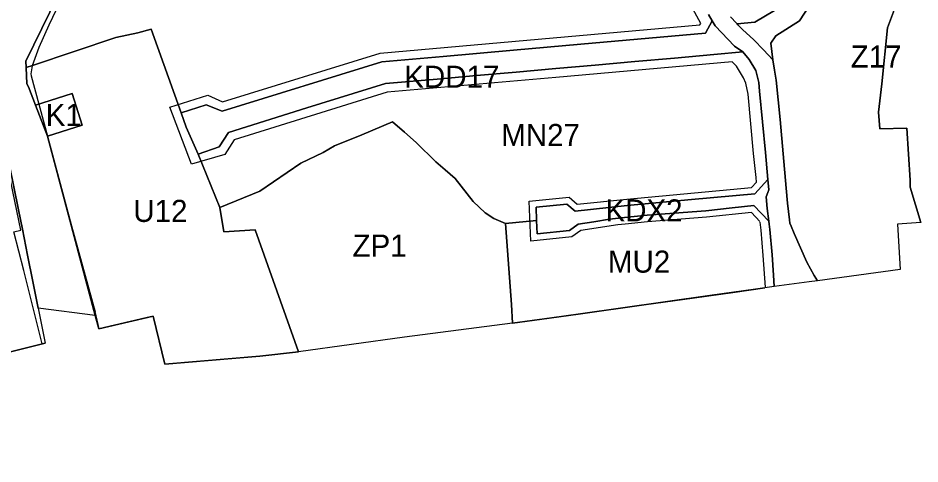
# Model space of a CAD drawing. Extents: x 7428841 to 7433518, y 5545054 to 5546840.
# Drawn here: x 7430252.9 to 7430661.7, y 5545108.1 to 5545310.2 of the extents above; entities that cross this region are included whole.
import ezdxf

# ---------------------------------------------------------------- set-up
doc = ezdxf.new("R2010")
doc.units = 0
for name, color, linetype in [('linie_rozgraniczajace', 7, 'Continuous'), ('linie_zabudowy_nieprzekraczalne', 7, 'Continuous'), ('oznaczenia_przeznaczen', 7, 'Continuous')]:
    doc.layers.add(name, color=color, linetype=linetype)

msp = doc.modelspace()

# ---------------------------------------------------------------- linework, layer by layer
at = {"layer": 'linie_rozgraniczajace'}
for points in [[(7430671.62, 5545396.42), (7430655.46, 5545383.04), (7430607.04, 5545308.84), (7430596.43, 5545302.16), (7430594.11, 5545298.72), (7430595.04, 5545291.17), (7430590.74, 5545295.75), (7430586.44, 5545300.33), (7430581.24, 5545305.02), (7430579.2, 5545307.11), (7430578.85, 5545307.47), (7430586.92, 5545308.36), (7430599.81, 5545316.06), (7430649.43, 5545392.37), (7430667.19, 5545405.74)], [(7430649.64, 5545312.97), (7430646.98, 5545305.71), (7430644.46, 5545280.38), (7430642.86, 5545267.43), (7430643.58, 5545259.98), (7430655.75, 5545260.21), (7430657.29, 5545236.72), (7430657.25, 5545233.5), (7430662.16, 5545217.46), (7430651.46, 5545216.69), (7430652.67, 5545196.27), (7430615.27, 5545191.14), (7430613.75, 5545193.47), (7430612.07, 5545196.52), (7430610.38, 5545199.57), (7430604.66, 5545212.59), (7430603.27, 5545215.9), (7430602.78, 5545217.26), (7430602.6, 5545218.73), (7430601.68, 5545226.2), (7430601.12, 5545233.04), (7430599.73, 5545248.63), (7430598.34, 5545264.21), (7430597.45, 5545273.08), (7430596.56, 5545281.95), (7430595.8, 5545286.56), (7430595.04, 5545291.17), (7430594.11, 5545298.72), (7430596.43, 5545302.16), (7430607.04, 5545308.84), (7430655.46, 5545383.04)], [(7430662.16, 5545217.46), (7430657.25, 5545233.5), (7430657.29, 5545236.72), (7430655.75, 5545260.21), (7430643.58, 5545259.98), (7430642.86, 5545267.43), (7430644.46, 5545280.38), (7430646.98, 5545305.71), (7430649.64, 5545312.97), (7430650.17, 5545314.36), (7430651.98, 5545318.53), (7430653.8, 5545322.71), (7430656.52, 5545327.37), (7430659.25, 5545332.04), (7430665.45, 5545338.74)], [(7430270.86, 5545320.33), (7430256.41, 5545290.6), (7430256.53, 5545287.68), (7430256.83, 5545280.36), (7430256.83, 5545280.35), (7430257.64, 5545278.96), (7430260.84, 5545270.63), (7430266.24, 5545256.61), (7430287.9, 5545175.34), (7430262, 5545178.72), (7430259.61, 5545190.72), (7430257.22, 5545202.69), (7430254.87, 5545214.45), (7430253.11, 5545223.25), (7430249.09, 5545243.33)], [(7430256.53, 5545287.68), (7430256.41, 5545290.6), (7430270.86, 5545320.33)], [(7430599.81, 5545316.06), (7430586.92, 5545308.36), (7430578.85, 5545307.47), (7430578.5, 5545307.83), (7430575.76, 5545310.63)], [(7430565.79, 5545311.83), (7430567.55, 5545308.83), (7430564.46, 5545303.28), (7430507.94, 5545298.3), (7430477.42, 5545295.59), (7430445.6, 5545292.79), (7430417.77, 5545290.33), (7430345.45, 5545267.96), (7430338.13, 5545270.81)], [(7430575.76, 5545310.63), (7430578.5, 5545307.83), (7430578.85, 5545307.47), (7430579.2, 5545307.11), (7430581.24, 5545305.02), (7430586.44, 5545300.33), (7430590.74, 5545295.75), (7430595.04, 5545291.17), (7430595.8, 5545286.56), (7430596.56, 5545281.95), (7430597.45, 5545273.08), (7430598.34, 5545264.21), (7430599.73, 5545248.63), (7430601.12, 5545233.04), (7430601.68, 5545226.2), (7430602.6, 5545218.73), (7430602.78, 5545217.26), (7430603.27, 5545215.9), (7430604.66, 5545212.59), (7430610.38, 5545199.57), (7430612.07, 5545196.52), (7430613.75, 5545193.47), (7430615.27, 5545191.14), (7430611.44, 5545190.62), (7430595.63, 5545188.44), (7430595.27, 5545193.69), (7430594.63, 5545202.81), (7430593.67, 5545214.38), (7430593.34, 5545216.69), (7430593.16, 5545218.14), (7430592.45, 5545223.91), (7430591.93, 5545229.07), (7430592.68, 5545231.05), (7430593.15, 5545232.36), (7430592.73, 5545237.03), (7430591.64, 5545249.22), (7430589.01, 5545277.08), (7430588.63, 5545280.9), (7430587.25, 5545286.36), (7430584.28, 5545291.3), (7430581.4, 5545294.77), (7430577.64, 5545297.41), (7430568.85, 5545306.6), (7430567.55, 5545308.83), (7430565.79, 5545311.83)], [(7430338.13, 5545270.81), (7430326.79, 5545267.2), (7430313.2, 5545305.05), (7430307.25, 5545303.45), (7430297.25, 5545301.41), (7430259.45, 5545288.63), (7430256.53, 5545287.68)], [(7430249.09, 5545243.33), (7430253.11, 5545223.25), (7430254.87, 5545214.45), (7430257.22, 5545202.69), (7430259.61, 5545190.72), (7430262, 5545178.72), (7430265.18, 5545162.82), (7430244.43, 5545157.62)]]:
    msp.add_lwpolyline(points, dxfattribs=at)
for points in [[(7430326.79, 5545267.2), (7430338.13, 5545270.81), (7430345.45, 5545267.96), (7430417.77, 5545290.33), (7430445.6, 5545292.79), (7430477.42, 5545295.59), (7430507.94, 5545298.3), (7430564.46, 5545303.28), (7430567.55, 5545308.83), (7430568.85, 5545306.6), (7430577.64, 5545297.41), (7430581.4, 5545294.77), (7430568.3, 5545293.58), (7430550.37, 5545292), (7430532.44, 5545290.42), (7430514.51, 5545288.83), (7430496.58, 5545287.25), (7430478.65, 5545285.66), (7430460.72, 5545284.09), (7430442.79, 5545282.5), (7430419.39, 5545280.44), (7430383.81, 5545269.4), (7430348.24, 5545258.36), (7430343.99, 5545251.76), (7430334.46, 5545248.51), (7430329.12, 5545260.68)], [(7430256.83, 5545280.35), (7430256.83, 5545280.36), (7430256.53, 5545287.68), (7430259.45, 5545288.63), (7430297.25, 5545301.41), (7430307.25, 5545303.45), (7430313.2, 5545305.05), (7430326.79, 5545267.2), (7430329.12, 5545260.68), (7430334.46, 5545248.51), (7430344.35, 5545224.34), (7430346.16, 5545213.28), (7430360.34, 5545214.12), (7430380.07, 5545158.83), (7430362.43, 5545156.9), (7430319.38, 5545153.37), (7430314.08, 5545175.08), (7430310.82, 5545174.3), (7430289.52, 5545169.27), (7430287.9, 5545175.34), (7430266.24, 5545256.61), (7430282, 5545261.6), (7430277.46, 5545275.9), (7430260.84, 5545270.63), (7430257.64, 5545278.96)], [(7430334.46, 5545248.51), (7430343.99, 5545251.76), (7430348.24, 5545258.36), (7430383.81, 5545269.4), (7430419.39, 5545280.44), (7430442.79, 5545282.5), (7430460.72, 5545284.09), (7430478.65, 5545285.66), (7430496.58, 5545287.25), (7430514.51, 5545288.83), (7430532.44, 5545290.42), (7430550.37, 5545292), (7430568.3, 5545293.58), (7430581.4, 5545294.77), (7430584.28, 5545291.3), (7430587.25, 5545286.36), (7430588.63, 5545280.9), (7430589.01, 5545277.08), (7430591.64, 5545249.22), (7430592.73, 5545237.03), (7430586.8, 5545230.5), (7430558.17, 5545227.85), (7430529.05, 5545225.15), (7430505.35, 5545222.68), (7430501.65, 5545225.81), (7430487.7, 5545224.42), (7430487.94, 5545218.41), (7430473.84, 5545217.01), (7430468.6, 5545219.37), (7430464.64, 5545221.93), (7430459.18, 5545226.95), (7430451.08, 5545237.43), (7430446.42, 5545241.41), (7430442.31, 5545244.93), (7430433.36, 5545253.83), (7430428, 5545258.44), (7430422.64, 5545263.05), (7430408.76, 5545257.21), (7430396.32, 5545252.19), (7430391.22, 5545249.26), (7430381.09, 5545244.37), (7430362.48, 5545231.65), (7430344.35, 5545224.34)], [(7430260.84, 5545270.63), (7430277.46, 5545275.9), (7430282, 5545261.6), (7430266.24, 5545256.61)], [(7430344.35, 5545224.34), (7430362.48, 5545231.65), (7430381.09, 5545244.37), (7430391.22, 5545249.26), (7430396.32, 5545252.19), (7430408.76, 5545257.21), (7430422.64, 5545263.05), (7430428, 5545258.44), (7430433.36, 5545253.83), (7430442.31, 5545244.93), (7430446.42, 5545241.41), (7430451.08, 5545237.43), (7430459.18, 5545226.95), (7430464.64, 5545221.93), (7430468.6, 5545219.37), (7430473.84, 5545217.01), (7430476.55, 5545180.32), (7430477.06, 5545171.9), (7430428.03, 5545165.48), (7430380.07, 5545158.83), (7430360.34, 5545214.12), (7430346.16, 5545213.28)], [(7430488.19, 5545212.41), (7430487.94, 5545218.41), (7430487.7, 5545224.42), (7430501.65, 5545225.81), (7430505.35, 5545222.68), (7430529.05, 5545225.15), (7430558.17, 5545227.85), (7430586.8, 5545230.5), (7430592.73, 5545237.03), (7430593.15, 5545232.36), (7430592.68, 5545231.05), (7430591.93, 5545229.07), (7430592.45, 5545223.91), (7430593.16, 5545218.14), (7430586.42, 5545225.19), (7430576.52, 5545224.11), (7430564.64, 5545222.84), (7430538, 5545220.82), (7430527.72, 5545219.76), (7430521, 5545218.95), (7430513.86, 5545217.87), (7430506.73, 5545216.78), (7430502.84, 5545213.87)], [(7430473.84, 5545217.01), (7430487.94, 5545218.41), (7430488.19, 5545212.41), (7430502.84, 5545213.87), (7430506.73, 5545216.78), (7430513.86, 5545217.87), (7430521, 5545218.95), (7430527.72, 5545219.76), (7430538, 5545220.82), (7430564.64, 5545222.84), (7430576.52, 5545224.11), (7430586.42, 5545225.19), (7430593.16, 5545218.14), (7430593.34, 5545216.69), (7430593.67, 5545214.38), (7430594.63, 5545202.81), (7430595.27, 5545193.69), (7430595.63, 5545188.44), (7430587.13, 5545187.28), (7430566.51, 5545184.41), (7430506.71, 5545175.93), (7430494.81, 5545174.24), (7430477.06, 5545171.9), (7430476.55, 5545180.32)]]:
    msp.add_lwpolyline(points, close=True, dxfattribs=at)
at = {"layer": 'linie_zabudowy_nieprzekraczalne'}
for points in [[(7430562.33, 5545307.67), (7430558.71, 5545314.33), (7430555.64, 5545321.98), (7430554.04, 5545330.27), (7430552.01, 5545348.62)], [(7430282.8, 5545340.62), (7430266.81, 5545306.93), (7430262.35, 5545296.84), (7430259.23, 5545288.47), (7430258.73, 5545284.93), (7430258.91, 5545283.96)], [(7430345.63, 5545272.15), (7430416.99, 5545294.28), (7430561.99, 5545307.08), (7430562.33, 5545307.67)], [(7430576.54, 5545290.37), (7430496.58, 5545283.23), (7430420.16, 5545276.49), (7430350.81, 5545254.97)], [(7430587.65, 5545235.85), (7430587.38, 5545237.88), (7430586.19, 5545248.71), (7430583.83, 5545275.69), (7430582.75, 5545280.62), (7430581.73, 5545283.04), (7430578.54, 5545288.33), (7430576.54, 5545290.37)], [(7430258.91, 5545283.96), (7430266.21, 5545256.68), (7430277.07, 5545215.98), (7430287.82, 5545177)], [(7430350.81, 5545254.97), (7430346.59, 5545248.34), (7430331.56, 5545243.96), (7430321.68, 5545269.8), (7430338.88, 5545275.14), (7430345.63, 5545272.15)], [(7430263.89, 5545162.52), (7430255.48, 5545195.72), (7430250.93, 5545213.22), (7430254.2, 5545214.02), (7430246.03, 5545253.5), (7430243.52, 5545254.3)], [(7430589.18, 5545217.99), (7430585.28, 5545222.05), (7430564.92, 5545219.86), (7430538.26, 5545217.83), (7430528.05, 5545216.78), (7430524.76, 5545216.38), (7430507.91, 5545213.92), (7430503.97, 5545210.97), (7430485.32, 5545209.11), (7430484.59, 5545227.12), (7430502.62, 5545228.92), (7430506.31, 5545225.8), (7430528.76, 5545228.14), (7430585.36, 5545233.38), (7430587.65, 5545235.85)], [(7430591.64, 5545188.17), (7430590.64, 5545202.51), (7430589.69, 5545213.97), (7430589.22, 5545217.63), (7430589.22, 5545217.63)], [(7429730.55, 5545206.18), (7429727.14, 5545167.45), (7429732.75, 5545160.67), (7429731.08, 5545153.27), (7429744.53, 5545151.94), (7429742.07, 5545126.13), (7429766.71, 5545119.71), (7429967.17, 5545110.46), (7430010.97, 5545109.36), (7430045.95, 5545108.72), (7430080.94, 5545108.08), (7430087.61, 5545109.15), (7430101.91, 5545108.31), (7430165.88, 5545119.44), (7430182.29, 5545142.3), (7430188.19, 5545137.46), (7430203.58, 5545142.22), (7430205.95, 5545138.43), (7430209.63, 5545136.23), (7430220.88, 5545133.1), (7430233.75, 5545137), (7430246.62, 5545140.9), (7430244.43, 5545157.62), (7430265.18, 5545162.82)], [(7430477.06, 5545171.9), (7430490.37, 5545173.65), (7430506.71, 5545175.93), (7430536.61, 5545180.17), (7430554.11, 5545182.65), (7430576.82, 5545185.84), (7430591.38, 5545187.86)], [(7430287.67, 5545177.13), (7430289.52, 5545169.27), (7430314.08, 5545175.08), (7430319.38, 5545153.37), (7430351.67, 5545156.02), (7430362.43, 5545156.9), (7430380.07, 5545158.83)]]:
    msp.add_lwpolyline(points, dxfattribs=at)

# ---------------------------------------------------------------- texts
at = {"layer": 'oznaczenia_przeznaczen'}
for s, p in [('Z17', (7430630.29, 5545287.72)), ('KDD17', (7430427.95, 5545278.56)), ('K1', (7430265.43, 5545261.25)), ('MN27', (7430471.91, 5545252.15)), ('U12', (7430305.14, 5545217.77)), ('KDX2', (7430519.16, 5545217.97)), ('ZP1', (7430404.5, 5545202.04)), ('MU2', (7430520.27, 5545194.77))]:
    msp.add_text(s, height=10, dxfattribs=at).set_placement(p)

doc.saveas('drawing.dxf')
